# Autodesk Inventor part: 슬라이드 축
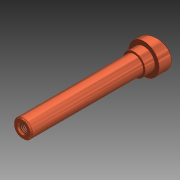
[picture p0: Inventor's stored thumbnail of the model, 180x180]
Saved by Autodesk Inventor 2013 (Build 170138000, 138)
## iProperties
Created: 2021-07
Part Number: 슬라이드 축
Document SubType Name: 모델링
Designer: mdu
Mass: 21.572 g
Surface Area: 67.5858 cm^2
Volume: 21.572 cm^3
Density: 1 g/cm^3
Material: 일반
변환 표준: STEP AP214IS
파일 이름: C:\Users\SeoGD\Desktop\?쒗뿕\異?stp
전처리기: Build: 253, Release: 2010 SP1 - Date: Wed 07/29/2009
전송 단위: 밀리미터
불확실성: 0.01
Author: mdu
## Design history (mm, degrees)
sketch "스케치1"
  geometry: L1 (0, 100)-(7.5, 100); L2 (7.5, 100)-(7.5, 0); L3 (7.5, 0)-(12.5, 0); L4 (12.5, 0)-(12.5, -17); L5 (12.5, -17)-(0, -17); L6 (0, -17)-(0, 100); 1 further point
  constraints: 12 end point, 2 parallel, 2 point on line, 1 perpendicular, 1 vertical
  dimensions: "d0" = 100 distance from line of L1 point (0, 0); "d1" = 15 diameter of L2 L6; "d2" = 25 diameter of L4 L6; "d3" = 17 distance of L3.end L4.end
revolve "회전1" sketch "스케치1" stored, may be unused: angle "d4" = 90 deg
sketch "스케치2"
  geometry: L1 (12.5, 0)-(12.5, -17) reference; L2 (-12.5, -17)-(12.5, -17) reference; L3 (-12.5, 0)-(-12.5, -17) reference; L4 (12.5, -5)-(-12.5, -11.699); L5 (-12.5, 0)-(12.5, 0) reference; 1 further point
  constraints: 2 end point, 2 point on line
  dimensions: "d5" = 75 deg angle of L1 L4; "d6" = 5 distance from line of L4.start L5
extrude "돌출1" cut sketch "스케치2" stored distance "d7" = 10; taper "d8" = 0 deg
chamfer "모따기1" distance "d9" = 1; stored, may be unused: second distance "d10" = 2, angle "d11" = 45 deg
fillet "모깎기1" dims "d12" = 0.5
hole "구멍1" diameter "d15" = 6.647; stored, may be unused: countersink angle "d19" = 90 deg, drill point angle "d21" = 118 deg; dims "d13" = 10, "d14" = 10, "d16" = 17, "d17" = 4, "d18" = 2, "d20" = 20
chamfer "모따기2" distance "d22" = 1; stored, may be unused: second distance "d23" = 2, angle "d24" = 45 deg
sketch "스케치3"
  geometry: C1 r 9 at (0, 0); 1 further point
  constraints: 1 centre point, 1 coincident
  dimensions: "d25" = 18 diameter of C1
extrude "돌출2" join sketch "스케치3" distance "d26" = 8; taper "d27" = 0 deg
node "솔리드1"
node "솔리드 본체"
node "곡면 본체"
node "솔리드2"
